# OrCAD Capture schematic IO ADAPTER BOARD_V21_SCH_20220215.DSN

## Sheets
1 01.TITLE: title: IO ADAPTER BOARD; rev: 2.1
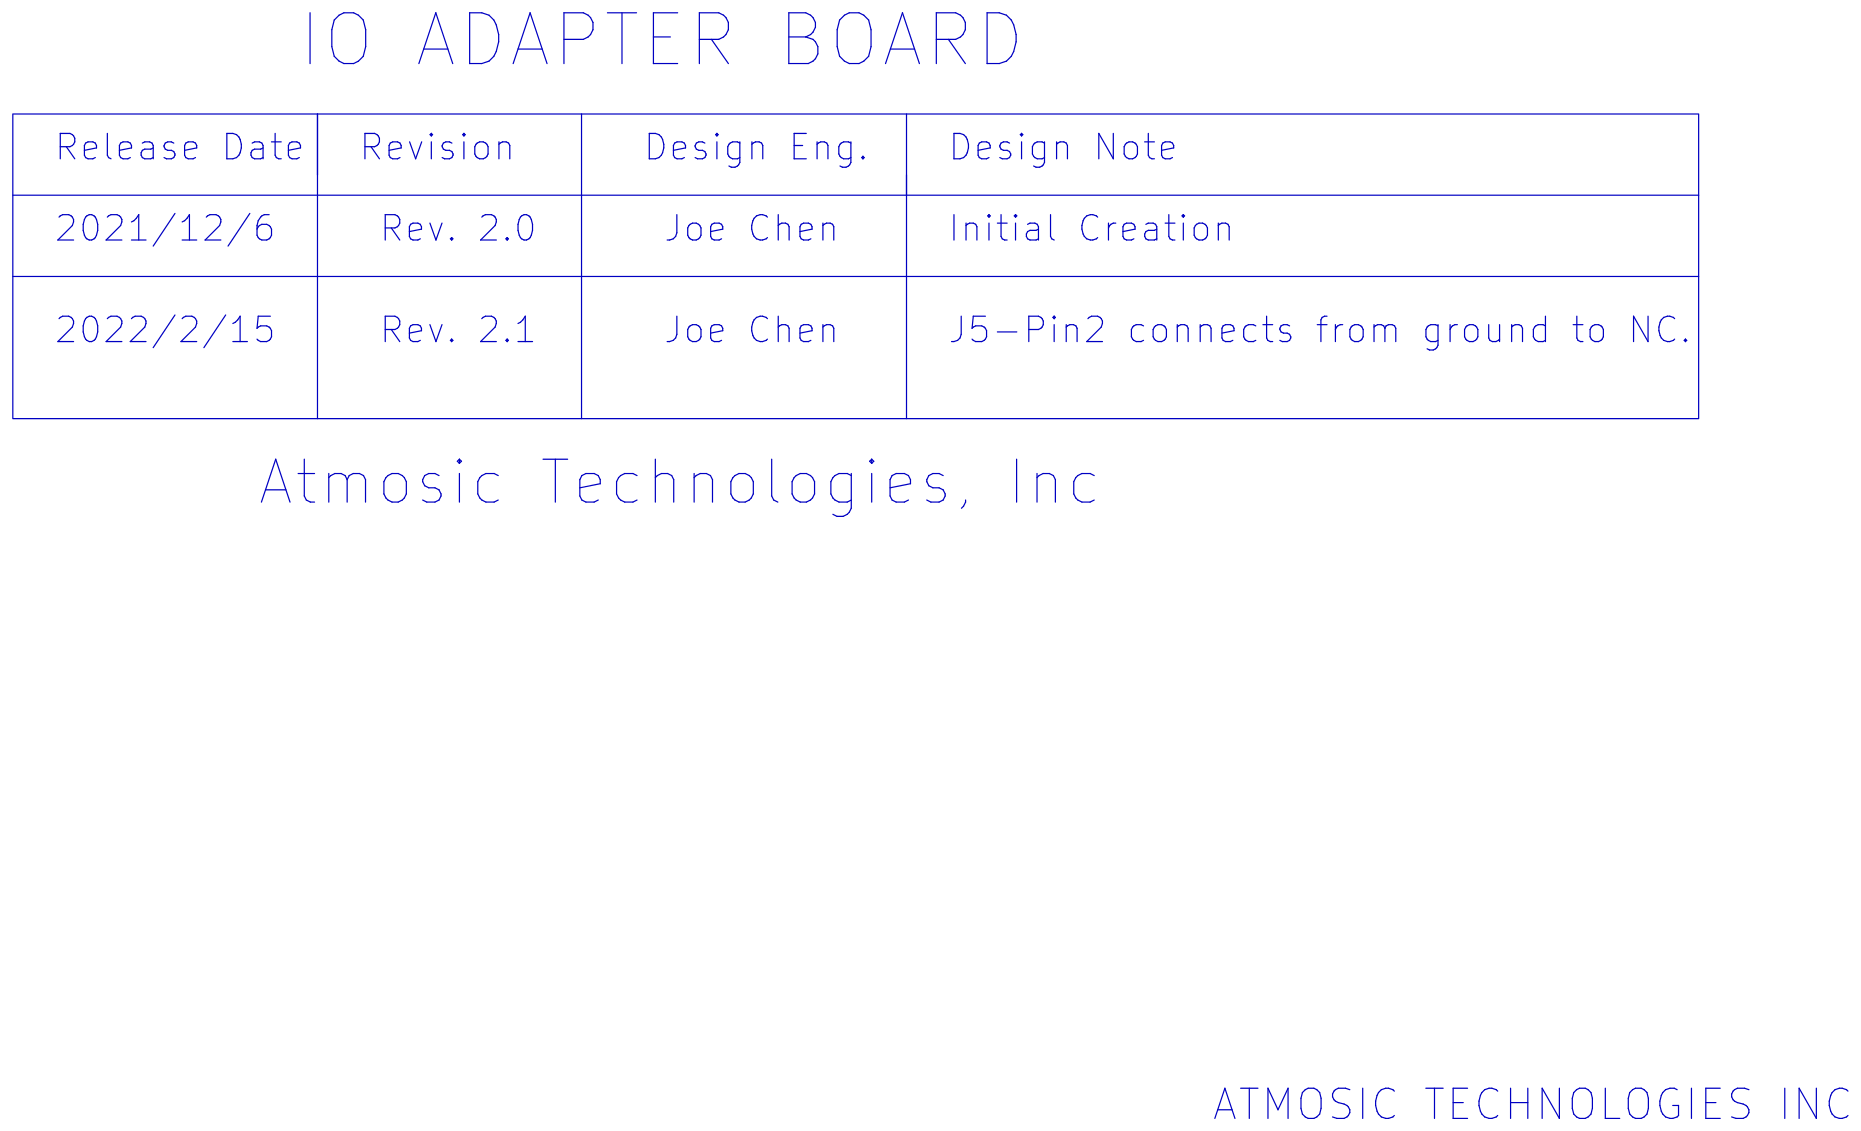
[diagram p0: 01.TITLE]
2 02_BLOCK: title: IO ADAPTER BOARD - BLOCK DIAGRAM
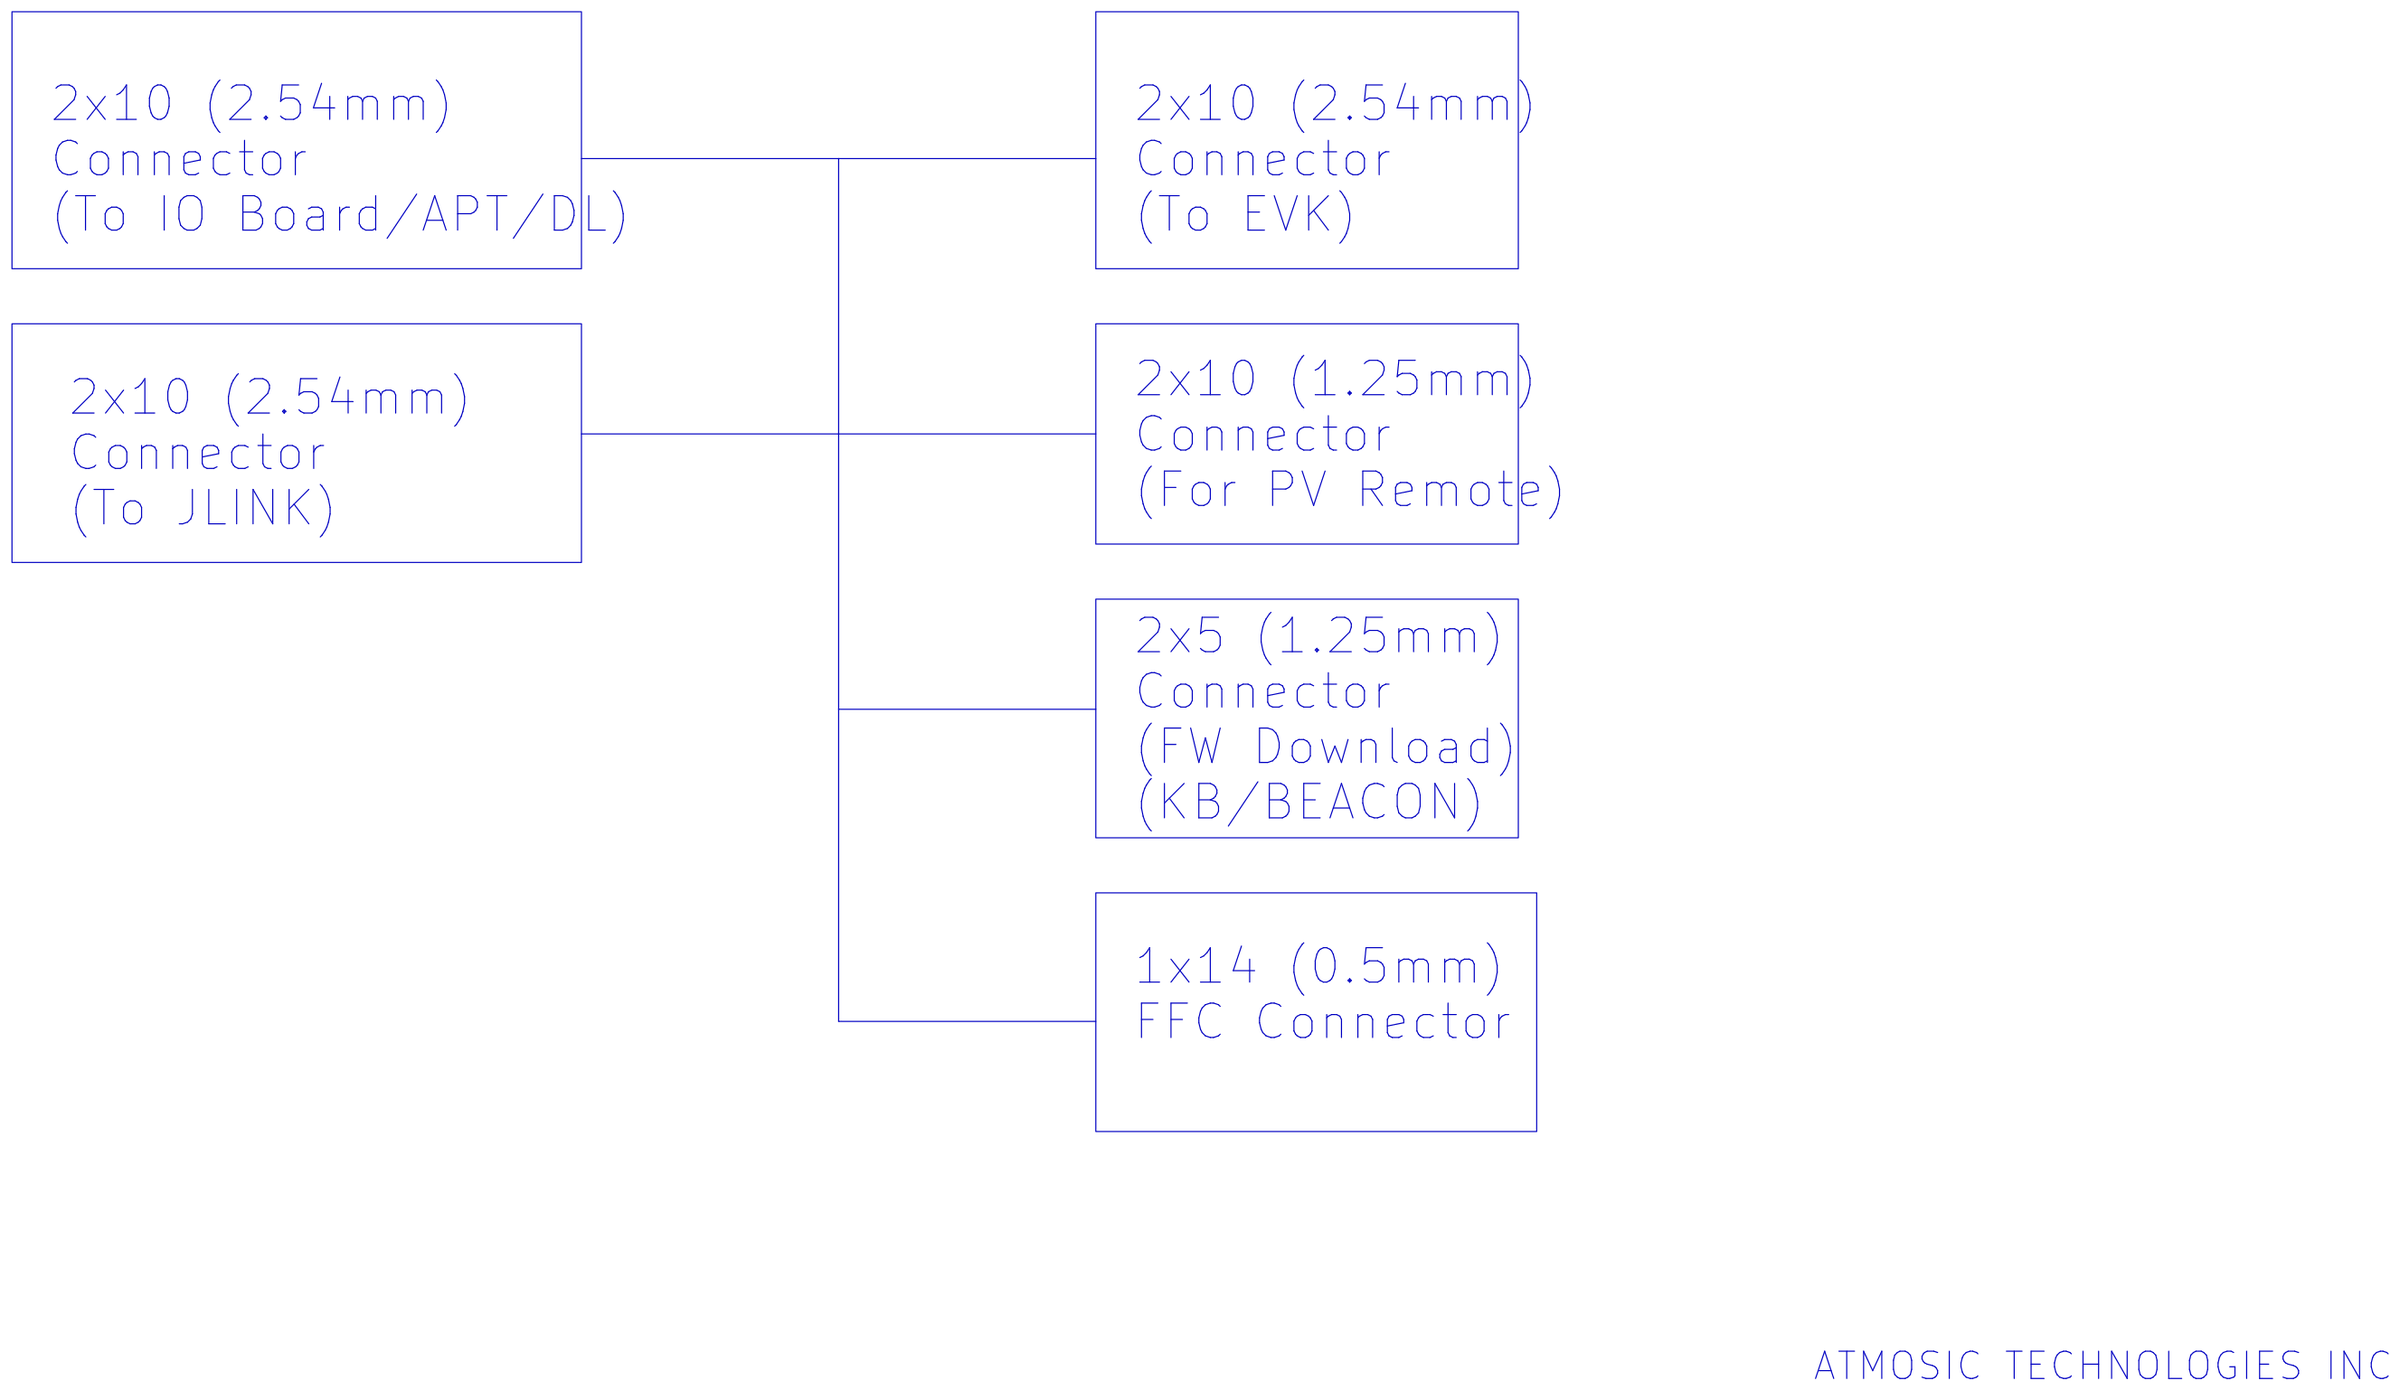
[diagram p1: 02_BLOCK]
3 03_IO BOARD: size B; title: IO ADAPTER BOARD - Main Circuit
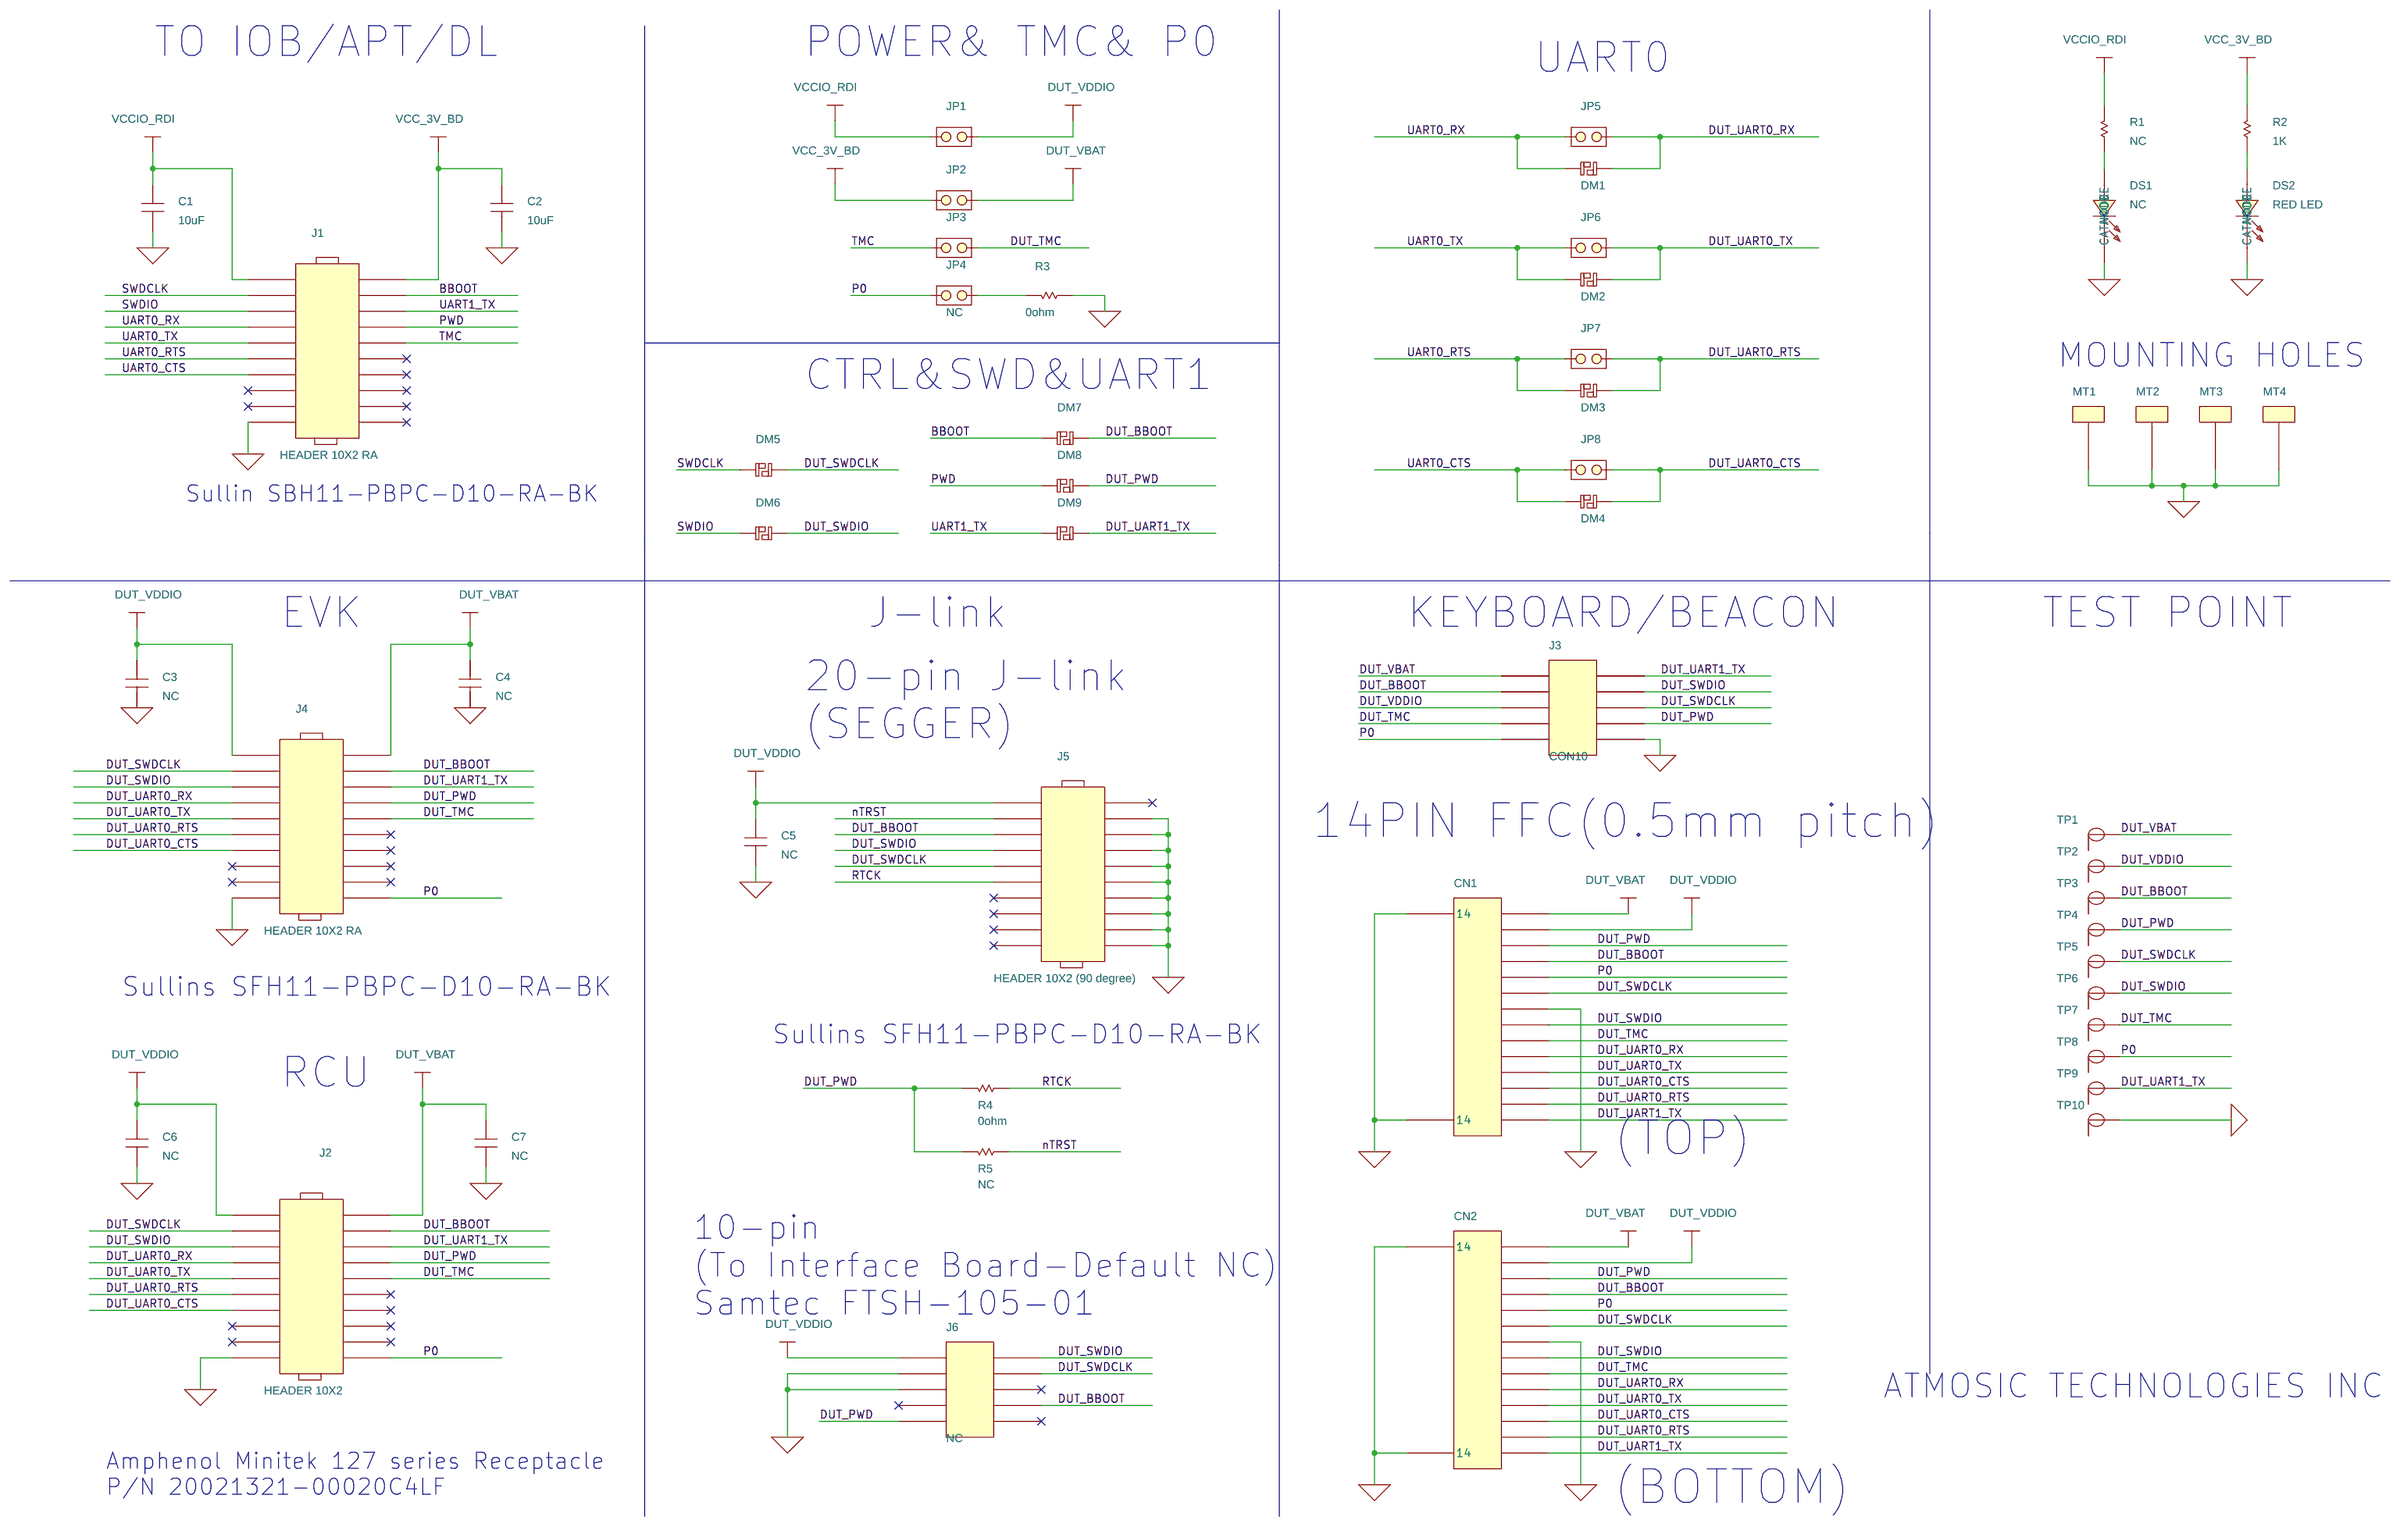
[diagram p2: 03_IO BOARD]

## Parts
C1  10uF  [0402]
C2  10uF  [0402]
C3  NC  [0402]
C4  NC  [0402]
C5  NC  [0402]
C6  NC  [0402]
C7  NC  [0402]
CN1  05002HR-14CE  [FFC/0.5mm/14PIN]
CN2  NC  [FFC/0.5mm/14PIN]
DM1  DUMMY  [0603-DUMMY]
DM2  DUMMY  [0603-DUMMY]
DM3  DUMMY  [0603-DUMMY]
DM4  DUMMY  [0603-DUMMY]
DM5  DUMMY  [0603-DUMMY]
DM6  DUMMY  [0603-DUMMY]
DM7  DUMMY  [0603-DUMMY]
DM8  DUMMY  [0603-DUMMY]
DM9  DUMMY  [0603-DUMMY]
DS1  NC  [LED-0603]
DS2  RED LED  [LED-0603]
J1  HEADER 10X2 RA  [HDR10X2-RT]
J2  HEADER 10X2  [CON-FCI-2X10-1.27MM-SMD-NO-MT]
J3  CON10  [CON_5X2_50MIL_SMD]
J4  HEADER 10X2 RA  [HDR10X2-RT-MATE]
J5  HEADER 10X2 (90 degree)  [HDR10X2-JLINK-1]
J6  NC  [CON_5X2_50MIL_SMD]
JP1  JUMPER-2  [HDR1X2]
JP2  JUMPER-2  [HDR1X2]
JP3  JUMPER-2  [HDR1X2]
JP4  NC  [HDR1X2]
JP5  NC  [HDR1X2]
JP6  NC  [HDR1X2]
JP7  NC  [HDR1X2]
JP8  NC  [HDR1X2]
MT1  TEST POINT  [HOLE-250R125]
MT2  TEST POINT  [HOLE-250R125]
MT3  TEST POINT  [HOLE-250R125]
MT4  TEST POINT  [HOLE-250R125]
R1  NC  [0402]
R2  1K  [0402]
R3  0ohm  [0402]
R4  0ohm  [0402]
R5  NC  [0402]
TP1  TP_0  [TP2]
TP2  TP_0  [TP2]
TP3  TP_0  [TP2]
TP4  TP_0  [TP2]
TP5  TP_0  [TP2]
TP6  TP_0  [TP2]
TP7  TP_0  [TP2]
TP8  TP_0  [TP2]
TP9  TP_0  [TP2]
TP10  TP_0  [TP2]

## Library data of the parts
C1 C2 = SMALL_CAP: Part Number: GRM155R60J106ME15D; Vendor: Murata Electronics
C3-C7 = SMALL_CAP
CN1 = FFC_14PIN_0.5MM_D: Part Number: 503480-1400; Vendor: MOLEX
CN2 = FFC_14PIN_0.5MM_D
DM1-DM9 = DUMMY: Part Number: AC0603JR-130RL; Vendor: YAGEO
DS1 = LED
DS2 = LED: Part Number: LTST-C191KRKT; Vendor: Lite-On Inc.
J1 = HEADER_10X2: Part Number: SBH11-PBPC-D10-RA-BK; Vendor: Sullins Connector Solutions
J2 = HEADER_10X2: Part Number: 20021321-00020C4LF; Vendor: Amphenol ICC (FCI)
J3 J6 = CON8_1
J4 J5 = HEADER_10X2: Part Number: SFH11-PBPC-D10-RA-BK; Vendor: Sullins Connector Solutions
JP1-JP3 = JUMPER-2: Part Number: 68000-102HLF; Vendor: Amphenol ICC (FCI)
JP4-JP8 = JUMPER-2
MT1-MT4 = TEST_POINT
R1 R5 = SMALL_R1
R2 = SMALL_R1: Part Number: WR04X1001FTL; Vendor: WALSIN
R3 R4 = SMALL_R1: Part Number: WR04X000PTL; Vendor: WALSIN
TP1-TP10 = TP_0

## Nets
GND_SIGNAL: C1.2 C2.2 C3.2 C4.2 C5.2 C6.2 C7.2 CN1.8 CN1.15(14) CN1.16(14) CN2.7 CN2.15(14) CN2.16(14) DS1.1(CATHODE) DS2.1(CATHODE) J1.19 J2.19 J3.10 J4.19 J5.4 J5.6 J5.8 J5.10 J5.12 J5.14 J5.16 J5.18 J5.20 J6.3 J6.5 MT1.1 MT2.1 MT3.1 MT4.1 R3.1 TP10.1(TP)
VCC_3V_BD: C2.1 J1.2 JP2.1 R2.2
VCCIO_RDI: C1.1 J1.1 JP1.1 R1.2
BBOOT: DM7.1 J1.4
DUT_BBOOT: CN1.11 CN2.4 DM7.2 J2.4 J3.3 J4.4 J5.5 J6.8 TP3.1(TP)
DUT_PWD: CN1.12 CN2.3 DM8.2 J2.8 J3.8 J4.8 J6.9 R4.2 R5.2 TP4.1(TP)
DUT_SWDCLK: CN1.9 CN2.6 DM5.2 J2.3 J3.6 J4.3 J5.9 J6.4 TP5.1(TP)
DUT_SWDIO: CN1.7 CN2.8 DM6.2 J2.5 J3.4 J4.5 J5.7 J6.2 TP6.1(TP)
DUT_TMC: CN1.6 CN2.9 J2.10 J3.7 J4.10 JP3.2 TP7.1(TP)
DUT_UART0_CTS: CN1.3 CN2.12 DM4.2 J2.13 J4.13 JP8.2
DUT_UART0_RTS: CN1.2 CN2.13 DM3.2 J2.11 J4.11 JP7.2
DUT_UART0_RX: CN1.5 CN2.10 DM1.2 J2.7 J4.7 JP5.2
DUT_UART0_TX: CN1.4 CN2.11 DM2.2 J2.9 J4.9 JP6.2
DUT_UART1_TX: CN1.1 CN2.14 DM9.2 J2.6 J3.2 J4.6 TP9.1(TP)
DUT_VBAT: C4.1 C7.1 CN1.14 CN2.1 J2.2 J3.1 J4.2 JP2.2 TP1.1(TP)
DUT_VDDIO: C3.1 C5.1 C6.1 CN1.13 CN2.2 J2.1 J3.5 J4.1 J5.1 J6.1 JP1.2 TP2.1(TP)
nTRST: J5.3 R5.1
P0: CN1.10 CN2.5 J2.20 J3.9 J4.20 JP4.1 TP8.1(TP)
PWD: DM8.1 J1.8
RTCK: J5.11 R4.1
SWDCLK: DM5.1 J1.3
SWDIO: DM6.1 J1.5
TMC: J1.10 JP3.1
UART0_CTS: DM4.1 J1.13 JP8.1
UART0_RTS: DM3.1 J1.11 JP7.1
UART0_RX: DM1.1 J1.7 JP5.1
UART0_TX: DM2.1 J1.9 JP6.1
UART1_TX: DM9.1 J1.6
N16861745: DS1.2(ANODE) R1.1
N16861801: DS2.2(ANODE) R2.1
N16870709: JP4.2 R3.2

Not connected (* = marked no-connect by the designer): J1 12* 14* 15* 16* 17* 18* 20*; J2 12* 14* 15* 16* 17* 18*; J4 12* 14* 15* 16* 17* 18*; J5 2* 13* 15* 17* 19*; J6 6* 7* 10*

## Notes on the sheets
sheet 1
- IO ADAPTER BOARD
- Release Date
- Revision
- Design Eng.
- Design Note
- 2021/12/6
- Rev. 2.0
- Joe Chen
- Initial Creation
- 2022/2/15
- Rev. 2.1
- Joe Chen
- J5-Pin2 connects from ground to NC.
- Atmosic Technologies, Inc
- ATMOSIC TECHNOLOGIES INC
sheet 2
- 2x10 (2.54mm)
  Connector
  (To IO Board/APT/DL)
- 2x10 (2.54mm)
  Connector
  (To EVK)
- 2x10 (1.25mm)
  Connector
  (For PV Remote)
- 2x10 (2.54mm)
  Connector
  (To JLINK)
- 2x5 (1.25mm)
  Connector
  (FW Download)
  (KB/BEACON)
- 1x14 (0.5mm)
  FFC Connector
- ATMOSIC TECHNOLOGIES INC
sheet 3
- TO IOB/APT/DL
- POWER& TMC& P0
- UART0
- MOUNTING HOLES
- CTRL&SWD&UART1
- Sullin SBH11-PBPC-D10-RA-BK
- EVK
- J-link
- KEYBOARD/BEACON
- TEST POINT
- 20-pin J-link
  (SEGGER)
- 14PIN FFC(0.5mm pitch)
- Sullins SFH11-PBPC-D10-RA-BK
- Sullins SFH11-PBPC-D10-RA-BK
- RCU
- (TOP)
- 10-pin
  (To Interface Board-Default NC)
  Samtec FTSH-105-01
- ATMOSIC TECHNOLOGIES INC
- Amphenol Minitek 127 series Receptacle
  P/N 20021321-00020C4LF
- (BOTTOM)
